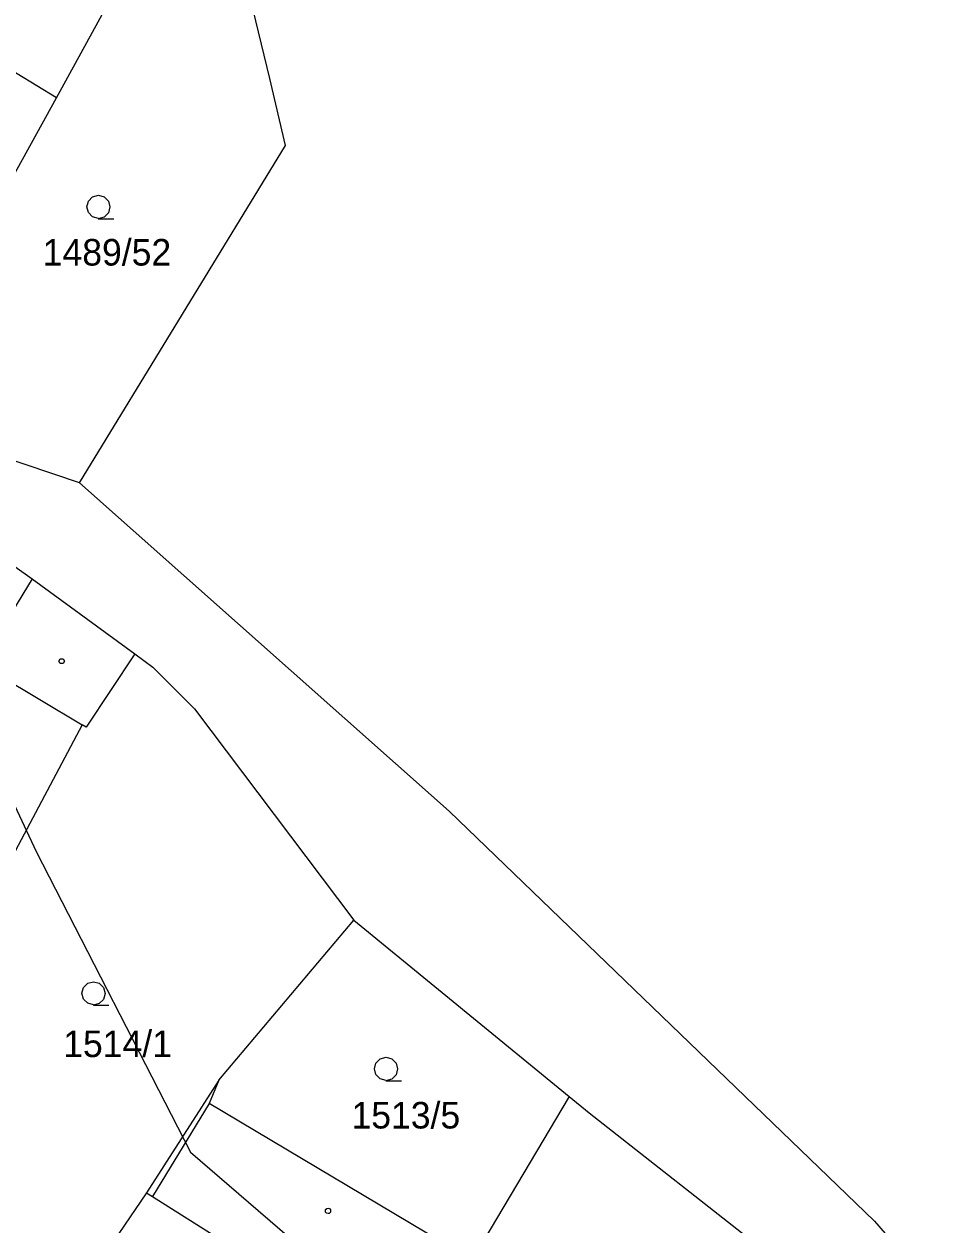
# Model space of a CAD drawing. Extents: x -779618 to -776429, y -1144546 to -1143350.
# Drawn here: x -777358.8 to -777300.1, y -1144294.1 to -1144217.4 of the extents above; entities that cross this region are included whole.
import ezdxf

# ---------------------------------------------------------------- set-up
doc = ezdxf.new("R2010")
doc.units = 0
for name, color, linetype in [('1', 7, 'Continuous'), ('11', 7, 'Continuous'), ('12', 7, 'Continuous'), ('2', 7, 'Continuous'), ('3', 7, 'Continuous'), ('4', 7, 'Continuous'), ('5', 7, 'Continuous')]:
    doc.layers.add(name, color=color, linetype=linetype)

msp = doc.modelspace()

# ---------------------------------------------------------------- linework, layer by layer
at = {"layer": '1'}
for p, q in [((-777356.7, -1144222.08), (-777374.2, -1144211.4)), ((-777356.7, -1144222.08), (-777350.76, -1144211.21)), ((-777343.07, -1144220.85), (-777344.48, -1144214.95)), ((-777342.05, -1144225.12), (-777343.07, -1144220.85)), ((-777367.97, -1144242.4), (-777356.7, -1144222.08)), ((-777355.24, -1144246.71), (-777342.05, -1144225.12)), ((-777355.24, -1144246.71), (-777361.44, -1144244.61)), ((-777355.24, -1144246.71), (-777331.58, -1144267.71)), ((-777363.75, -1144248.98), (-777358.26, -1144252.86)), ((-777358.26, -1144252.86), (-777351.69, -1144257.65)), ((-777351.69, -1144257.65), (-777354.8, -1144262.35)), ((-777351.69, -1144257.65), (-777350.54, -1144258.5)), ((-777350.54, -1144258.5), (-777347.89, -1144261.18)), ((-777347.89, -1144261.18), (-777337.68, -1144274.7)), ((-777355.06, -1144262.2), (-777363.47, -1144277.95)), ((-777354.8, -1144262.35), (-777355.06, -1144262.2)), ((-777331.58, -1144267.71), (-777304.39, -1144293.94)), ((-777346.32, -1144284.92), (-777337.68, -1144274.7)), ((-777337.68, -1144274.7), (-777323.91, -1144285.97)), ((-777346.32, -1144284.92), (-777350.95, -1144292.13)), ((-777346.32, -1144284.92), (-777346.95, -1144286.41)), ((-777323.91, -1144285.97), (-777330.12, -1144296.43)), ((-777323.91, -1144285.97), (-777322.64, -1144287.01)), ((-777330.12, -1144296.43), (-777346.95, -1144286.41)), ((-777322.64, -1144287.01), (-777308.26, -1144298.31)), ((-777350.95, -1144292.13), (-777352.71, -1144294.74)), ((-777350.95, -1144292.13), (-777350.57, -1144292.37)), ((-777350.57, -1144292.37), (-777332.32, -1144303.86)), ((-777304.39, -1144293.94), (-777300.2, -1144298.73))]:
    msp.add_line(p, q, dxfattribs=at)
at = {"layer": '11'}
msp.add_lwpolyline([(-777401.89, -1144091.82), (-777401.74, -1144108.7), (-777400.37, -1144141.15), (-777400.21, -1144144.96), (-777399.57, -1144148.4), (-777397.77, -1144158.1), (-777396.41, -1144165.46), (-777391.38, -1144188.33), (-777391.37, -1144188.38), (-777390.2, -1144193.69), (-777389.61, -1144196.42), (-777386.34, -1144211.31), (-777377.7, -1144229.35), (-777372.3, -1144239.9), (-777371.54, -1144241.39), (-777366, -1144253.23), (-777358.01, -1144270.3), (-777348.13, -1144289.54), (-777328.66, -1144306.32), (-777310.4, -1144318.27), (-777301.04, -1144322.44), (-777300.13, -1144323.03)], dxfattribs=at)
at = {"layer": '12'}
for p, q in [((-777346.95, -1144286.41), (-777350.57, -1144292.37)), ((-777330.12, -1144296.43), (-777346.95, -1144286.41)), ((-777350.57, -1144292.37), (-777332.32, -1144303.86))]:
    msp.add_line(p, q, dxfattribs=at)
at = {"layer": '3'}
for points in [[(-777354.02, -1144229.79), (-777354.4, -1144229.69), (-777354.67, -1144229.42), (-777354.77, -1144229.05), (-777354.67, -1144228.68), (-777354.4, -1144228.41), (-777354.03, -1144228.31), (-777353.66, -1144228.41), (-777353.39, -1144228.68), (-777353.29, -1144229.06), (-777353.39, -1144229.44), (-777353.66, -1144229.71), (-777354.04, -1144229.81), (-777353.04, -1144229.81)], [(-777354.33, -1144280.11), (-777354.71, -1144280.01), (-777354.98, -1144279.74), (-777355.08, -1144279.37), (-777354.98, -1144279), (-777354.71, -1144278.73), (-777354.34, -1144278.63), (-777353.97, -1144278.73), (-777353.7, -1144279), (-777353.6, -1144279.38), (-777353.7, -1144279.76), (-777353.97, -1144280.03), (-777354.35, -1144280.13), (-777353.35, -1144280.13)], [(-777335.62, -1144284.94), (-777336, -1144284.84), (-777336.27, -1144284.57), (-777336.37, -1144284.2), (-777336.27, -1144283.83), (-777336, -1144283.56), (-777335.63, -1144283.46), (-777335.26, -1144283.56), (-777334.99, -1144283.83), (-777334.89, -1144284.21), (-777334.99, -1144284.59), (-777335.26, -1144284.86), (-777335.64, -1144284.96), (-777334.64, -1144284.96)]]:
    msp.add_lwpolyline(points, dxfattribs=at)
at = {"layer": '4'}
for p, q in [((-777358.26, -1144252.86), (-777361.6, -1144258.3)), ((-777361.6, -1144258.3), (-777355.06, -1144262.2)), ((-777346.95, -1144286.41), (-777350.57, -1144292.37))]:
    msp.add_line(p, q, dxfattribs=at)
at = {"layer": '5'}
for points in [[(-777356.29, -1144257.97), (-777356.2, -1144258.12), (-777356.29, -1144258.27), (-777356.47, -1144258.27), (-777356.56, -1144258.12), (-777356.47, -1144257.97)], [(-777339.34, -1144293.12), (-777339.24, -1144293.14), (-777339.19, -1144293.23), (-777339.17, -1144293.29), (-777339.19, -1144293.38), (-777339.27, -1144293.45), (-777339.34, -1144293.46), (-777339.43, -1144293.43), (-777339.49, -1144293.37), (-777339.51, -1144293.29), (-777339.49, -1144293.2), (-777339.41, -1144293.13)]]:
    msp.add_lwpolyline(points, close=True, dxfattribs=at)

# ---------------------------------------------------------------- texts
at = {"layer": '2'}
for s, p in [('1489/52', (-777357.587, -1144232.81)), ('1514/1', (-777356.277, -1144283.45)), ('1513/5', (-777337.837, -1144288.02))]:
    msp.add_text(s, height=1.7, dxfattribs=at).set_placement(p)

doc.saveas('drawing.dxf')
